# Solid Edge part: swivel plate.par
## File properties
Author: Deepak Maini
Template: Normal.par
Last saved by: Robert a Rhodes jr
Revision: 14
Application: Solid Edge
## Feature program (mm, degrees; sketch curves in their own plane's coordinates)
sketch for "unnamed Protrusion 1" #1 plane through (0, 0, 0) normal (0, -1, 0) x-axis (1, 0, 0)
  arc centre (0, -70.1687) radius 96 from (-30.5455, 20.8422) to (30.5455, 20.8422) cw
  arc centre (28, 13.258) radius 8 from (30.5455, 20.8422) to (25.4545, 5.6737) cw
  arc centre (0, -70.1687) radius 80 from (-25.4545, 5.6737) to (25.4545, 5.6737) cw
  arc centre (-28, 13.258) radius 8 from (-30.5455, 20.8422) to (-25.4545, 5.6737) ccw
sketch for "unnamed Protrusion 1" #2 plane through (0, 0, 0) normal (0, -1, 0) x-axis (1, 0, 0)
  line (-50, 33.3929) -> (-50, -93.7302)
  arc centre (0, 9.8313) radius 115 from (-50, -93.7302) to (50, -93.7302) ccw
  line (50, -93.7302) -> (50, 33.3929)
  arc centre (0, -70.1687) radius 115 from (-50, 33.3929) to (50, 33.3929) cw
extrude "unnamed Protrusion 1" add finite 20 symmetric
sketch for "unnamed Hole 1" plane through (0, -10, -12.9456) normal (0, -1, 0) x-axis (0, 0, -1)
  hole centre (57.2231, 0) bore radius 12
hole "unnamed Hole 1" through
sketch for "unnamed Protrusion 2" plane through (0, -10, -12.9456) normal (0, -1, 0) x-axis (0, 0, -1)
  line (80.7847, 50) -> (2.2231, 50)
  line (2.2231, 50) -> (2.2231, -50)
  line (2.2231, -50) -> (80.7847, -50)
  arc centre (-22.7769, 0) radius 115 from (80.7847, -50) to (80.7847, 50) ccw
extrude "unnamed Protrusion 2" add finite 30 along +normal
sketch for "unnamed Cutout 1" plane through (0, -40, -60.1687) normal (0, -1, 0) x-axis (0, 0, -1)
  line (-45, 33) -> (-45, -33)
  line (-45, -33) -> (66.5839, -33)
  line (66.5839, -33) -> (66.5839, 33)
  line (66.5839, 33) -> (-45, 33)
extrude "unnamed Cutout 1" cut finite 31 along -normal
sketch for "unnamed Hole 2" plane through (50, -15, -30.1686) normal (1, 0, 0) x-axis (0, 0, 1)
  hole centre (1, 10) bore radius 7
  dimension (linear) = 1
hole "unnamed Hole 2" through
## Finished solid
Body 1: solid body, 23 faces, 54 edges, 30 vertices.
  Faces by surface: plane 13, cylinder 10
  Edges by curve: line 32, circle 22
Bounding box of the edges (mm): 100.000 x 50.000 x 150.000, from (-50, -40, -105.1687) to (50, 10, 44.8313).
Cylindrical faces by radius (mm): R7 x2, R8 x2, R12 x1, R14 x1, R80 x1, R96 x1, R115 x2
Planar faces by outward normal: +x 2, +y 1, +z 2, -x 2, -y 5, -z 1
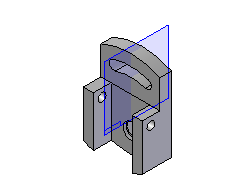
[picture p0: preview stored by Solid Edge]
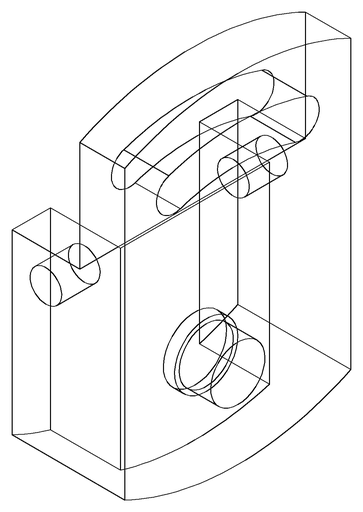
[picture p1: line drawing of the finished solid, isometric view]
